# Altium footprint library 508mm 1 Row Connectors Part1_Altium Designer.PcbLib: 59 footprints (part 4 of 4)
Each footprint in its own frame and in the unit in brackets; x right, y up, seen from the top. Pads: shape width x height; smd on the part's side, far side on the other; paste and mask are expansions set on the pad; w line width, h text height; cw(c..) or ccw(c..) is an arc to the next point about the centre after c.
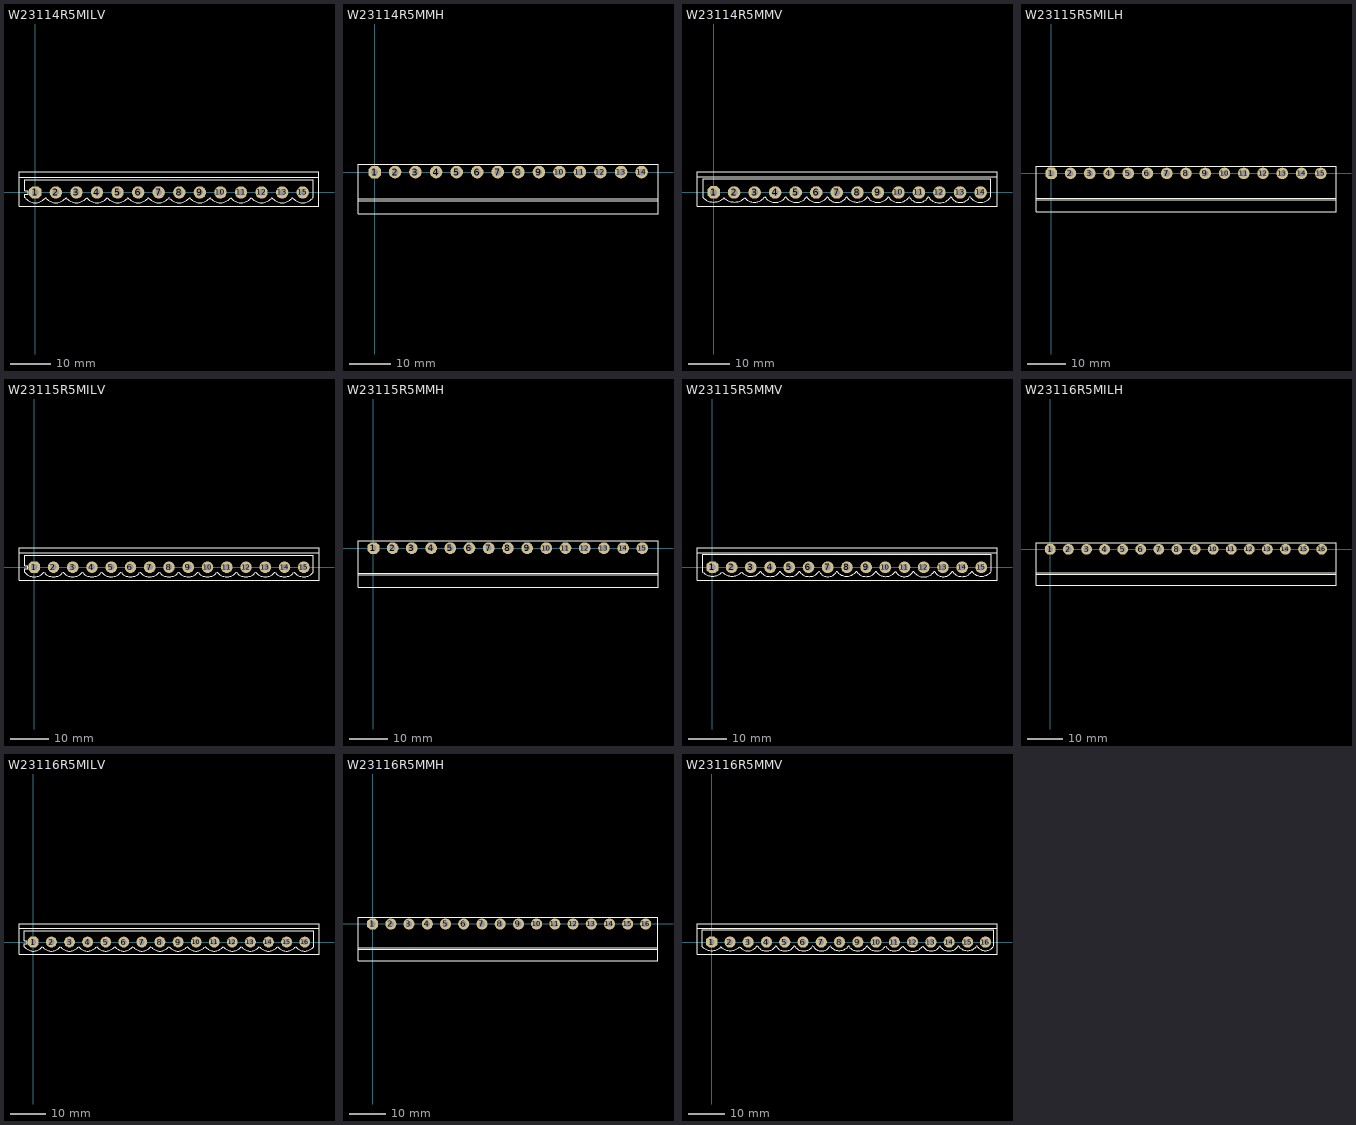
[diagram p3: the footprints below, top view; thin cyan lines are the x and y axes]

## W23114R5MILV [mil] "M.Hariri (Altium Designer)"
pads (14):
  oct 120x120 hole 62.99: 1(0,0)
  round 120 hole 62.99: 2(200,0) 3(400,0) 4(600,0) 5(800,0) 6(1000,0) 7(1200,0) 8(1400,0) 9(1600,0) 10(1800,0) 11(2000,0) 12(2200,0) 13(2400,0) 15(2600,0)
Top Overlay:
  lines w8: -158.33,150 2758.33,150 ; -100,-50 -100,-16.67 -66.67,-16.67 -66.67,16.67 -100,16.67 -100,125 2700,125 2700,-50 ; -99.83,-50.23 ccw(c0,25) 99.83,-50.23 ; 100.17,-50.23 ccw(c200,25) 299.83,-50.23 ; 300.17,-50.23 ccw(c400,25) 499.83,-50.23 ; 500.17,-50.23 ccw(c600,25) 699.83,-50.23 ; 700.17,-50.23 ccw(c800,25) 899.83,-50.23 ; 900.17,-50.23 ccw(c1000,25) 1099.83,-50.23 ; 1100.17,-50.23 ccw(c1200,25) 1299.83,-50.23 ; 1300.17,-50.23 ccw(c1400,25) 1499.83,-50.23 ; 1500.17,-50.23 ccw(c1600,25) 1699.83,-50.23 ; 1700.17,-50.23 ccw(c1800,25) 1899.83,-50.23 ; 1900.17,-50.23 ccw(c2000,25) 2099.83,-50.23 ; 2100.17,-50.23 ccw(c2200,25) 2299.83,-50.23 ; 2300.17,-50.23 ccw(c2400,25) 2499.83,-50.23 ; 2500.17,-50.23 ccw(c2600,25) 2699.83,-50.23 ; -158.33,-133.33 2758.33,-133.33 2758.33,200 -158.33,200 -158.33,-133.33

## W23114R5MMH [mil] "M.Hariri (Altium Designer)"
pads (14):
  oct 120x120 hole 62.99: 1(0,0)
  round 120 hole 62.99: 2(196.67,0) 3(391.67,0) 4(590.83,0) 5(787.5,0) 6(984.17,0) 7(1180.83,0) 8(1378.33,0) 9(1575,0) 10(1771.67,0) 11(1968.33,0) 12(2165,0) 13(2362.5,0) 14(2559.17,0)
Top Overlay:
  lines w8: -158.33,-275 2716.67,-275 ; -158.33,-258.33 2716.67,-258.33 ; -158.33,-400 -158.33,75 2716.67,75 2716.67,-400 -158.33,-400

## W23114R5MMV [mil] "M.Hariri (Altium Designer)"
pads (14):
  oct 120x120 hole 62.99: 1(0,0)
  round 120 hole 62.99: 2(196.67,0) 3(393.33,0) 4(590.83,0) 5(787.5,0) 6(984.17,0) 7(1180.83,0) 8(1378.33,0) 9(1575,0) 10(1771.67,0) 11(1968.33,0) 12(2165,0) 13(2362.5,0) 14(2559.17,0)
Top Overlay:
  lines w8: -158.33,150 2716.67,150 ; -100.17,-50.17 ccw(c0,50) 100.17,-50.17 ; -100,-50 -100,133.33 2658.33,133.33 2658.33,-41.67 ; 99.83,-50.17 ccw(c200,50) 300.17,-50.17 ; 299.7,-49.47 ccw(c391.67,25) 489.77,-41.17 ; 492.18,-42.1 ccw(c591.67,25) 691.15,-42.1 ; 692.18,-42.1 ccw(c791.67,25) 891.15,-42.1 ; 892.18,-42.1 ccw(c991.67,25) 1091.15,-42.1 ; 1092.23,-42.17 ccw(c1183.33,8.33) 1274.44,-42.17 ; 1275.17,-41.89 ccw(c1375,33.33) 1474.83,-41.89 ; 1475.52,-42.1 ccw(c1575,25) 1674.48,-42.1 ; 1675.52,-42.1 ccw(c1775,25) 1872.08,-45.53 ; 1875.56,-42.17 ccw(c1966.67,8.33) 2057.77,-42.17 ; 2058.81,-42.19 ccw(c2166.67,33.33) 2274.52,-42.19 ; 2275.56,-42.17 ccw(c2366.67,8.33) 2457.77,-42.17 ; 2458.85,-42.1 ccw(c2558.33,25) 2657.82,-42.1 ; -158.33,-133.33 2716.67,-133.33 2716.67,200 -158.33,200 -158.33,-133.33

## W23115R5MILH [mil] "M.Hariri (Altium Designer)"
pads (15):
  oct 120x120 hole 62.99: 1(0,0)
  round 120 hole 62.99: 2(200,0) 3(400,0) 4(600,0) 5(800,0) 6(1000,0) 7(1200,0) 8(1400,0) 9(1600,0) 10(1800,0) 11(2000,0) 12(2200,0) 13(2400,0) 14(2600,0) 15(2800,0)
Top Overlay:
  lines w8: -158.33,-275 2958.33,-275 ; -158.33,-258.33 2958.33,-258.33 ; -158.33,-400 -158.33,75 2958.33,75 2958.33,-400 -158.33,-400

## W23115R5MILV [mil] "M.Hariri (Altium Designer)"
pads (15):
  oct 120x120 hole 62.99: 1(0,0)
  round 120 hole 62.99: 2(200,0) 3(400,0) 4(600,0) 5(800,0) 6(1000,0) 7(1200,0) 8(1400,0) 9(1600,0) 10(1800,0) 11(2000,0) 12(2200,0) 13(2400,0) 14(2600,0) 15(2800,0)
Top Overlay:
  lines w8: -158.33,150 2958.33,150 ; -100,-50 -100,-16.67 -66.67,-16.67 -66.67,16.67 -100,16.67 -100,125 2900,125 2900,-50 ; -99.83,-50.23 ccw(c0,25) 99.83,-50.23 ; 100.17,-50.23 ccw(c200,25) 299.83,-50.23 ; 300.17,-50.23 ccw(c400,25) 499.83,-50.23 ; 500.17,-50.23 ccw(c600,25) 699.83,-50.23 ; 700.17,-50.23 ccw(c800,25) 899.83,-50.23 ; 900.17,-50.23 ccw(c1000,25) 1099.83,-50.23 ; 1100.17,-50.23 ccw(c1200,25) 1299.83,-50.23 ; 1300.17,-50.23 ccw(c1400,25) 1499.83,-50.23 ; 1500.17,-50.23 ccw(c1600,25) 1699.83,-50.23 ; 1700.17,-50.23 ccw(c1800,25) 1899.83,-50.23 ; 1900.17,-50.23 ccw(c2000,25) 2099.83,-50.23 ; 2100.17,-50.23 ccw(c2200,25) 2299.83,-50.23 ; 2300.17,-50.23 ccw(c2400,25) 2499.83,-50.23 ; 2500.17,-50.23 ccw(c2600,25) 2699.83,-50.23 ; 2700.17,-50.23 ccw(c2800,25) 2899.83,-50.23 ; -158.33,-133.33 -158.33,200 2958.33,200 2958.33,-133.33 -158.33,-133.33

## W23115R5MMH [mil] "M.Hariri (Altium Designer)"
pads (15):
  oct 120x120 hole 62.99: 1(0,0)
  round 120 hole 62.99: 2(196.67,0) 3(391.67,0) 4(590.83,0) 5(787.5,0) 6(984.17,0) 7(1180.83,0) 8(1378.33,0) 9(1575,0) 10(1771.67,0) 11(1968.33,0) 12(2165,0) 13(2362.5,0) 14(2559.17,0) 15(2755.83,0)
Top Overlay:
  lines w8: -158.33,-275 2916.67,-275 ; -158.33,-258.33 2916.67,-258.33 ; -158.33,-400 2916.67,-400 2916.67,75 -158.33,75 -158.33,-400

## W23115R5MMV [mil] "M.Hariri (Altium Designer)"
pads (15):
  oct 120x120 hole 62.99: 1(0,0)
  round 120 hole 62.99: 2(196.67,0) 3(393.33,0) 4(590.83,0) 5(787.5,0) 6(984.17,0) 7(1180.83,0) 8(1378.33,0) 9(1575,0) 10(1771.67,0) 11(1968.33,0) 12(2165,0) 13(2362.5,0) 14(2559.17,0) 15(2755.83,0)
Top Overlay:
  lines w8: -158.33,150 2916.67,150 ; -100.17,-50.17 ccw(c0,50) 100.17,-50.17 ; -100,-50 -100,133.33 2858.33,133.33 2858.33,-41.67 ; 99.83,-50.17 ccw(c200,50) 300.17,-50.17 ; 299.7,-49.47 ccw(c391.67,25) 489.77,-41.17 ; 492.18,-42.1 ccw(c591.67,25) 691.15,-42.1 ; 692.18,-42.1 ccw(c791.67,25) 891.15,-42.1 ; 892.18,-42.1 ccw(c991.67,25) 1091.15,-42.1 ; 1092.23,-42.17 ccw(c1183.33,8.33) 1274.44,-42.17 ; 1275.17,-41.89 ccw(c1375,33.33) 1474.83,-41.89 ; 1475.52,-42.1 ccw(c1575,25) 1674.48,-42.1 ; 1675.52,-42.1 ccw(c1775,25) 1872.08,-45.53 ; 1875.56,-42.17 ccw(c1966.67,8.33) 2057.77,-42.17 ; 2058.81,-42.19 ccw(c2166.67,33.33) 2274.52,-42.19 ; 2275.56,-42.17 ccw(c2366.67,8.33) 2457.77,-42.17 ; 2458.85,-42.1 ccw(c2558.33,25) 2657.82,-42.1 ; 2658.5,-41.89 ccw(c2758.33,33.33) 2858.16,-41.89 ; -158.33,-133.33 -158.33,200 2916.67,200 2916.67,-133.33 -158.33,-133.33

## W23116R5MILH [mil] "M.Hariri (Altium Designer)"
pads (16):
  oct 120x120 hole 62.99: 1(0,0)
  round 120 hole 62.99: 2(200,0) 3(400,0) 4(600,0) 5(800,0) 6(1000,0) 7(1200,0) 8(1400,0) 9(1600,0) 10(1800,0) 11(2000,0) 12(2200,0) 13(2400,0) 14(2600,0) 15(2800,0) 16(3000,0)
Top Overlay:
  lines w8: -158.33,-275 3158.33,-275 ; -158.33,-258.33 3158.33,-258.33 ; -158.33,-400 3158.33,-400 3158.33,75 -158.33,75 -158.33,-400

## W23116R5MILV [mil] "M.Hariri (Altium Designer)"
pads (16):
  oct 120x120 hole 62.99: 1(0,0)
  round 120 hole 62.99: 2(200,0) 3(400,0) 4(600,0) 5(800,0) 6(1000,0) 7(1200,0) 8(1400,0) 9(1600,0) 10(1800,0) 11(2000,0) 12(2200,0) 13(2400,0) 14(2600,0) 15(2800,0) 16(3000,0)
Top Overlay:
  lines w8: -158.33,150 3158.33,150 ; -100,-50 -100,-16.67 -66.67,-16.67 -66.67,16.67 -100,16.67 -100,125 3100,125 3100,-50 ; -99.83,-50.23 ccw(c0,25) 99.83,-50.23 ; 100.17,-50.23 ccw(c200,25) 299.83,-50.23 ; 300.17,-50.23 ccw(c400,25) 499.83,-50.23 ; 500.17,-50.23 ccw(c600,25) 699.83,-50.23 ; 700.17,-50.23 ccw(c800,25) 899.83,-50.23 ; 900.17,-50.23 ccw(c1000,25) 1099.83,-50.23 ; 1100.17,-50.23 ccw(c1200,25) 1299.83,-50.23 ; 1300.17,-50.23 ccw(c1400,25) 1499.83,-50.23 ; 1500.17,-50.23 ccw(c1600,25) 1699.83,-50.23 ; 1700.17,-50.23 ccw(c1800,25) 1899.83,-50.23 ; 1900.17,-50.23 ccw(c2000,25) 2099.83,-50.23 ; 2100.17,-50.23 ccw(c2200,25) 2299.83,-50.23 ; 2300.17,-50.23 ccw(c2400,25) 2499.83,-50.23 ; 2500.17,-50.23 ccw(c2600,25) 2699.83,-50.23 ; 2700.17,-50.23 ccw(c2800,25) 2899.83,-50.23 ; 2900.17,-50.23 ccw(c3000,25) 3099.83,-50.23 ; -158.33,-133.33 3158.33,-133.33 3158.33,200 -158.33,200 -158.33,-133.33

## W23116R5MMH [mil] "M.Hariri (Altium Designer)"
pads (16):
  oct 120x120 hole 62.99: 1(0,0)
  round 120 hole 62.99: 2(196.67,0) 3(391.67,0) 4(590.83,0) 5(787.5,0) 6(984.17,0) 7(1180.83,0) 8(1378.33,0) 9(1575,0) 10(1771.67,0) 11(1968.33,0) 12(2165,0) 13(2362.5,0) 14(2559.17,0) 15(2755.83,0) 16(2950,0)
Top Overlay:
  lines w8: -158.33,-275 3083.33,-275 ; -158.33,-258.33 3083.33,-258.33 ; -158.33,-400 -158.33,75 3083.33,75 3083.33,-400 -158.33,-400

## W23116R5MMV [mil] "M.Hariri (Altium Designer)"
pads (16):
  oct 120x120 hole 62.99: 1(0,0)
  round 120 hole 62.99: 2(196.67,0) 3(393.33,0) 4(590.83,0) 5(787.5,0) 6(984.17,0) 7(1180.83,0) 8(1378.33,0) 9(1575,0) 10(1771.67,0) 11(1968.33,0) 12(2165,0) 13(2362.5,0) 14(2559.17,0) 15(2758.33,0) 16(2950,0)
Top Overlay:
  lines w8: -158.33,150 3075,150 ; -100.17,-50.17 ccw(c0,50) 100.17,-50.17 ; -100,-50 -100,133.33 3041.67,133.33 3041.67,-41.67 ; 99.83,-50.17 ccw(c200,50) 300.17,-50.17 ; 299.7,-49.47 ccw(c391.67,25) 489.77,-41.17 ; 492.18,-42.1 ccw(c591.67,25) 691.15,-42.1 ; 692.18,-42.1 ccw(c791.67,25) 891.15,-42.1 ; 892.18,-42.1 ccw(c991.67,25) 1091.15,-42.1 ; 1092.23,-42.17 ccw(c1183.33,8.33) 1274.44,-42.17 ; 1275.17,-41.89 ccw(c1375,33.33) 1474.83,-41.89 ; 1475.52,-42.1 ccw(c1575,25) 1674.48,-42.1 ; 1675.52,-42.1 ccw(c1775,25) 1872.08,-45.53 ; 1875.56,-42.17 ccw(c1966.67,8.33) 2057.77,-42.17 ; 2058.81,-42.19 ccw(c2166.67,33.33) 2274.52,-42.19 ; 2275.56,-42.17 ccw(c2366.67,8.33) 2457.77,-42.17 ; 2458.85,-42.1 ccw(c2558.33,25) 2657.82,-42.1 ; 2658.5,-41.89 ccw(c2758.33,33.33) 2858.16,-41.89 ; 2858.13,-40.74 ccw(c2950,16.67) 3041.87,-40.74 ; -158.33,-133.33 -158.33,200 3075,200 3075,-133.33 -158.33,-133.33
